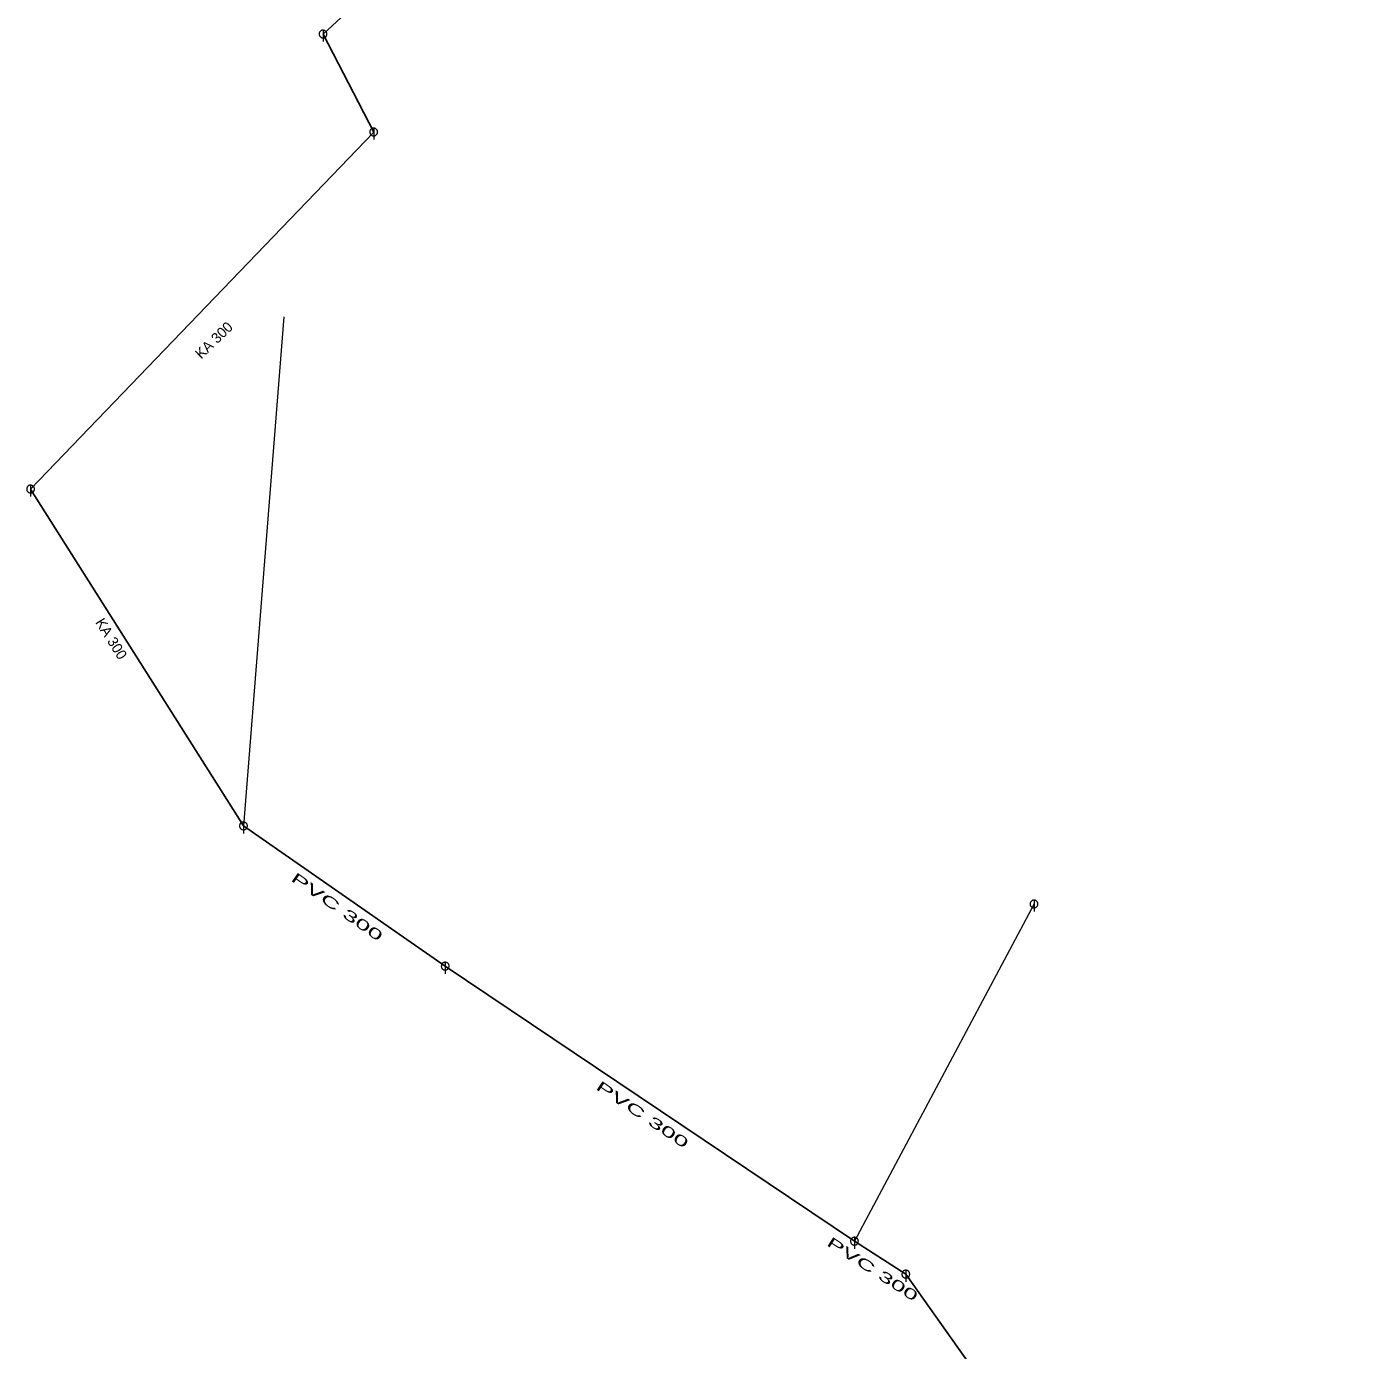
# Model space of a CAD drawing. Extents: x -687468 to -685917, y -974192 to -973456.
# Drawn here: x -686081.4 to -685995.3, y -973957.1 to -973871.6 of the extents above; entities that cross this region are included whole.
import ezdxf
from ezdxf.enums import TextEntityAlignment as Align

# ---------------------------------------------------------------- set-up
doc = ezdxf.new("R2010")
doc.units = 0
doc.header["$LTSCALE"] = 0.27
for name, color, linetype, lineweight in [('1', 7, 'Continuous', 13), ('11', 7, 'Continuous', 13), ('14', 7, 'Continuous', 25), ('22', 7, 'Continuous', 13)]:
    doc.layers.add(name, color=color, linetype=linetype, lineweight=lineweight)

msp = doc.modelspace()

# ---------------------------------------------------------------- linework, layer by layer
at = {"layer": '11'}
for p, q in [((-686064.802, -973890.376), (-686067.399, -973923.264)), ((-686016.339, -973928.308), (-686027.937, -973950.093))]:
    msp.add_line(p, q, dxfattribs=at)
at = {"layer": '14'}
for p, q in [((-686045.47, -973856.659), (-686062.261, -973872.109)), ((-686062.261, -973872.109), (-686058.989, -973878.439)), ((-686058.989, -973878.439), (-686081.151, -973901.503)), ((-686081.151, -973901.503), (-686067.399, -973923.264)), ((-686067.399, -973923.264), (-686054.369, -973932.324)), ((-686054.369, -973932.324), (-686027.937, -973950.093)), ((-686027.937, -973950.093), (-686024.619, -973952.22)), ((-686024.619, -973952.22), (-685995.262, -973993.552))]:
    msp.add_line(p, q, dxfattribs=at)
at = {"layer": '22'}
for p, q in [((-686062.26, -973871.857), (-686062.261, -973872.601)), ((-686058.988, -973878.187), (-686058.989, -973878.931)), ((-686081.15, -973901.251), (-686081.151, -973901.995)), ((-686067.398, -973923.012), (-686067.399, -973923.755)), ((-686016.338, -973928.056), (-686016.339, -973928.799)), ((-686054.368, -973932.072), (-686054.369, -973932.816)), ((-686027.936, -973949.841), (-686027.937, -973950.585)), ((-686024.618, -973951.968), (-686024.619, -973952.712))]:
    msp.add_line(p, q, dxfattribs=at)
for points in [[(-686062.009, -973872.109), (-686062.01, -973872.083), (-686062.014, -973872.057), (-686062.02, -973872.031), (-686062.03, -973872.007), (-686062.042, -973871.983), (-686062.056, -973871.961), (-686062.073, -973871.94), (-686062.091, -973871.922), (-686062.112, -973871.905), (-686062.134, -973871.891), (-686062.158, -973871.879), (-686062.182, -973871.869), (-686062.208, -973871.863), (-686062.234, -973871.859), (-686062.26, -973871.857), (-686062.286, -973871.858), (-686062.312, -973871.862), (-686062.338, -973871.868), (-686062.363, -973871.878), (-686062.386, -973871.89), (-686062.408, -973871.904), (-686062.429, -973871.921), (-686062.447, -973871.939), (-686062.464, -973871.96), (-686062.478, -973871.982), (-686062.49, -973872.006), (-686062.5, -973872.03), (-686062.507, -973872.056), (-686062.511, -973872.082), (-686062.513, -973872.108), (-686062.512, -973872.134), (-686062.508, -973872.16), (-686062.501, -973872.186), (-686062.491, -973872.211), (-686062.479, -973872.234), (-686062.465, -973872.256), (-686062.448, -973872.277), (-686062.43, -973872.295), (-686062.409, -973872.312), (-686062.387, -973872.326), (-686062.364, -973872.338), (-686062.339, -973872.348), (-686062.313, -973872.355), (-686062.287, -973872.359), (-686062.261, -973872.361), (-686062.235, -973872.36), (-686062.209, -973872.356), (-686062.183, -973872.349), (-686062.159, -973872.339), (-686062.135, -973872.327), (-686062.113, -973872.313), (-686062.092, -973872.296), (-686062.074, -973872.278), (-686062.057, -973872.257), (-686062.043, -973872.235), (-686062.031, -973872.212), (-686062.021, -973872.187), (-686062.015, -973872.161), (-686062.011, -973872.135)], [(-686058.737, -973878.439), (-686058.738, -973878.413), (-686058.742, -973878.387), (-686058.748, -973878.361), (-686058.758, -973878.337), (-686058.77, -973878.313), (-686058.784, -973878.291), (-686058.801, -973878.27), (-686058.819, -973878.252), (-686058.84, -973878.235), (-686058.862, -973878.221), (-686058.886, -973878.209), (-686058.91, -973878.199), (-686058.936, -973878.193), (-686058.962, -973878.189), (-686058.988, -973878.187), (-686059.014, -973878.188), (-686059.04, -973878.192), (-686059.066, -973878.198), (-686059.091, -973878.208), (-686059.114, -973878.22), (-686059.136, -973878.234), (-686059.157, -973878.251), (-686059.175, -973878.269), (-686059.192, -973878.29), (-686059.206, -973878.312), (-686059.218, -973878.336), (-686059.228, -973878.36), (-686059.235, -973878.386), (-686059.239, -973878.412), (-686059.24, -973878.438), (-686059.24, -973878.464), (-686059.236, -973878.49), (-686059.229, -973878.516), (-686059.219, -973878.541), (-686059.207, -973878.564), (-686059.193, -973878.586), (-686059.176, -973878.607), (-686059.158, -973878.625), (-686059.137, -973878.642), (-686059.115, -973878.656), (-686059.092, -973878.668), (-686059.067, -973878.678), (-686059.041, -973878.685), (-686059.015, -973878.689), (-686058.989, -973878.691), (-686058.963, -973878.69), (-686058.937, -973878.686), (-686058.911, -973878.679), (-686058.887, -973878.669), (-686058.863, -973878.657), (-686058.841, -973878.643), (-686058.82, -973878.626), (-686058.802, -973878.608), (-686058.785, -973878.587), (-686058.771, -973878.565), (-686058.759, -973878.542), (-686058.749, -973878.517), (-686058.743, -973878.491), (-686058.739, -973878.465)], [(-686080.899, -973901.503), (-686080.9, -973901.477), (-686080.904, -973901.451), (-686080.91, -973901.425), (-686080.92, -973901.401), (-686080.932, -973901.377), (-686080.946, -973901.355), (-686080.963, -973901.334), (-686080.981, -973901.316), (-686081.002, -973901.299), (-686081.024, -973901.285), (-686081.048, -973901.273), (-686081.072, -973901.263), (-686081.098, -973901.257), (-686081.124, -973901.253), (-686081.15, -973901.251), (-686081.176, -973901.252), (-686081.202, -973901.256), (-686081.228, -973901.262), (-686081.253, -973901.272), (-686081.276, -973901.284), (-686081.298, -973901.298), (-686081.319, -973901.315), (-686081.337, -973901.333), (-686081.354, -973901.354), (-686081.368, -973901.376), (-686081.38, -973901.4), (-686081.39, -973901.424), (-686081.397, -973901.45), (-686081.401, -973901.476), (-686081.402, -973901.502), (-686081.402, -973901.528), (-686081.398, -973901.554), (-686081.391, -973901.58), (-686081.381, -973901.605), (-686081.369, -973901.628), (-686081.355, -973901.65), (-686081.338, -973901.671), (-686081.32, -973901.689), (-686081.299, -973901.706), (-686081.277, -973901.72), (-686081.254, -973901.732), (-686081.229, -973901.742), (-686081.203, -973901.749), (-686081.177, -973901.753), (-686081.151, -973901.755), (-686081.125, -973901.754), (-686081.099, -973901.75), (-686081.073, -973901.743), (-686081.049, -973901.733), (-686081.025, -973901.721), (-686081.003, -973901.707), (-686080.982, -973901.69), (-686080.964, -973901.672), (-686080.947, -973901.651), (-686080.933, -973901.629), (-686080.921, -973901.606), (-686080.911, -973901.581), (-686080.905, -973901.555), (-686080.901, -973901.529)], [(-686067.147, -973923.264), (-686067.148, -973923.238), (-686067.152, -973923.212), (-686067.158, -973923.186), (-686067.168, -973923.162), (-686067.18, -973923.138), (-686067.194, -973923.116), (-686067.211, -973923.095), (-686067.229, -973923.077), (-686067.25, -973923.06), (-686067.272, -973923.046), (-686067.296, -973923.034), (-686067.32, -973923.024), (-686067.346, -973923.018), (-686067.372, -973923.014), (-686067.398, -973923.012), (-686067.424, -973923.013), (-686067.45, -973923.017), (-686067.476, -973923.023), (-686067.501, -973923.033), (-686067.524, -973923.045), (-686067.546, -973923.059), (-686067.567, -973923.076), (-686067.585, -973923.094), (-686067.602, -973923.115), (-686067.616, -973923.137), (-686067.628, -973923.161), (-686067.638, -973923.185), (-686067.645, -973923.211), (-686067.649, -973923.237), (-686067.651, -973923.263), (-686067.65, -973923.289), (-686067.646, -973923.315), (-686067.639, -973923.341), (-686067.629, -973923.366), (-686067.617, -973923.389), (-686067.603, -973923.411), (-686067.586, -973923.432), (-686067.568, -973923.45), (-686067.547, -973923.467), (-686067.525, -973923.481), (-686067.502, -973923.493), (-686067.477, -973923.503), (-686067.451, -973923.51), (-686067.425, -973923.514), (-686067.399, -973923.516), (-686067.373, -973923.515), (-686067.347, -973923.511), (-686067.321, -973923.504), (-686067.297, -973923.494), (-686067.273, -973923.482), (-686067.251, -973923.468), (-686067.23, -973923.451), (-686067.212, -973923.433), (-686067.195, -973923.412), (-686067.181, -973923.39), (-686067.169, -973923.367), (-686067.159, -973923.342), (-686067.153, -973923.316), (-686067.149, -973923.29)], [(-686016.087, -973928.308), (-686016.088, -973928.282), (-686016.092, -973928.256), (-686016.098, -973928.23), (-686016.108, -973928.206), (-686016.12, -973928.182), (-686016.134, -973928.16), (-686016.151, -973928.139), (-686016.169, -973928.121), (-686016.19, -973928.104), (-686016.212, -973928.09), (-686016.236, -973928.078), (-686016.26, -973928.068), (-686016.286, -973928.062), (-686016.312, -973928.058), (-686016.338, -973928.056), (-686016.364, -973928.057), (-686016.39, -973928.061), (-686016.416, -973928.067), (-686016.441, -973928.077), (-686016.464, -973928.089), (-686016.486, -973928.103), (-686016.507, -973928.12), (-686016.525, -973928.138), (-686016.542, -973928.159), (-686016.556, -973928.181), (-686016.568, -973928.205), (-686016.578, -973928.229), (-686016.585, -973928.255), (-686016.589, -973928.281), (-686016.591, -973928.307), (-686016.59, -973928.333), (-686016.586, -973928.359), (-686016.579, -973928.385), (-686016.569, -973928.41), (-686016.557, -973928.433), (-686016.543, -973928.455), (-686016.526, -973928.476), (-686016.508, -973928.494), (-686016.487, -973928.511), (-686016.465, -973928.525), (-686016.442, -973928.537), (-686016.417, -973928.547), (-686016.391, -973928.554), (-686016.365, -973928.558), (-686016.339, -973928.559), (-686016.313, -973928.559), (-686016.287, -973928.555), (-686016.261, -973928.548), (-686016.237, -973928.538), (-686016.213, -973928.526), (-686016.191, -973928.512), (-686016.17, -973928.495), (-686016.152, -973928.477), (-686016.135, -973928.456), (-686016.121, -973928.434), (-686016.109, -973928.411), (-686016.099, -973928.386), (-686016.093, -973928.36), (-686016.089, -973928.334)], [(-686054.117, -973932.324), (-686054.118, -973932.298), (-686054.122, -973932.272), (-686054.128, -973932.246), (-686054.138, -973932.222), (-686054.15, -973932.198), (-686054.164, -973932.176), (-686054.181, -973932.155), (-686054.199, -973932.137), (-686054.22, -973932.12), (-686054.242, -973932.106), (-686054.266, -973932.094), (-686054.29, -973932.084), (-686054.316, -973932.078), (-686054.342, -973932.074), (-686054.368, -973932.072), (-686054.394, -973932.073), (-686054.42, -973932.077), (-686054.446, -973932.083), (-686054.471, -973932.093), (-686054.494, -973932.105), (-686054.516, -973932.119), (-686054.537, -973932.136), (-686054.555, -973932.154), (-686054.572, -973932.175), (-686054.586, -973932.197), (-686054.598, -973932.221), (-686054.608, -973932.245), (-686054.615, -973932.271), (-686054.619, -973932.297), (-686054.62, -973932.323), (-686054.62, -973932.349), (-686054.616, -973932.375), (-686054.609, -973932.401), (-686054.599, -973932.426), (-686054.587, -973932.449), (-686054.573, -973932.471), (-686054.556, -973932.492), (-686054.538, -973932.51), (-686054.517, -973932.527), (-686054.495, -973932.541), (-686054.472, -973932.553), (-686054.447, -973932.563), (-686054.421, -973932.57), (-686054.395, -973932.574), (-686054.369, -973932.576), (-686054.343, -973932.575), (-686054.317, -973932.571), (-686054.291, -973932.564), (-686054.267, -973932.554), (-686054.243, -973932.542), (-686054.221, -973932.528), (-686054.2, -973932.511), (-686054.182, -973932.493), (-686054.165, -973932.472), (-686054.151, -973932.45), (-686054.139, -973932.427), (-686054.129, -973932.402), (-686054.123, -973932.376), (-686054.119, -973932.35)], [(-686027.685, -973950.093), (-686027.686, -973950.067), (-686027.69, -973950.041), (-686027.696, -973950.015), (-686027.706, -973949.991), (-686027.718, -973949.967), (-686027.732, -973949.945), (-686027.749, -973949.924), (-686027.767, -973949.906), (-686027.788, -973949.889), (-686027.81, -973949.875), (-686027.834, -973949.863), (-686027.858, -973949.853), (-686027.884, -973949.847), (-686027.91, -973949.843), (-686027.936, -973949.841), (-686027.962, -973949.842), (-686027.988, -973949.846), (-686028.014, -973949.852), (-686028.039, -973949.862), (-686028.062, -973949.874), (-686028.084, -973949.888), (-686028.105, -973949.905), (-686028.123, -973949.923), (-686028.14, -973949.944), (-686028.154, -973949.966), (-686028.166, -973949.99), (-686028.176, -973950.014), (-686028.183, -973950.04), (-686028.187, -973950.066), (-686028.189, -973950.092), (-686028.188, -973950.118), (-686028.184, -973950.144), (-686028.177, -973950.17), (-686028.167, -973950.195), (-686028.155, -973950.218), (-686028.141, -973950.24), (-686028.124, -973950.261), (-686028.106, -973950.279), (-686028.085, -973950.296), (-686028.063, -973950.31), (-686028.04, -973950.322), (-686028.015, -973950.332), (-686027.989, -973950.339), (-686027.963, -973950.343), (-686027.937, -973950.345), (-686027.911, -973950.344), (-686027.885, -973950.34), (-686027.859, -973950.333), (-686027.835, -973950.323), (-686027.811, -973950.311), (-686027.789, -973950.297), (-686027.768, -973950.28), (-686027.75, -973950.262), (-686027.733, -973950.241), (-686027.719, -973950.219), (-686027.707, -973950.196), (-686027.697, -973950.171), (-686027.691, -973950.145), (-686027.687, -973950.119)], [(-686024.367, -973952.22), (-686024.368, -973952.194), (-686024.372, -973952.168), (-686024.378, -973952.142), (-686024.388, -973952.118), (-686024.4, -973952.094), (-686024.414, -973952.072), (-686024.431, -973952.051), (-686024.449, -973952.033), (-686024.47, -973952.016), (-686024.492, -973952.002), (-686024.516, -973951.99), (-686024.54, -973951.98), (-686024.566, -973951.974), (-686024.592, -973951.97), (-686024.618, -973951.968), (-686024.644, -973951.969), (-686024.67, -973951.973), (-686024.696, -973951.979), (-686024.721, -973951.989), (-686024.744, -973952.001), (-686024.766, -973952.015), (-686024.787, -973952.032), (-686024.805, -973952.05), (-686024.822, -973952.071), (-686024.836, -973952.093), (-686024.848, -973952.117), (-686024.858, -973952.141), (-686024.865, -973952.167), (-686024.869, -973952.193), (-686024.87, -973952.219), (-686024.87, -973952.245), (-686024.866, -973952.271), (-686024.859, -973952.297), (-686024.849, -973952.322), (-686024.837, -973952.345), (-686024.823, -973952.367), (-686024.806, -973952.388), (-686024.788, -973952.406), (-686024.767, -973952.423), (-686024.745, -973952.437), (-686024.722, -973952.449), (-686024.697, -973952.459), (-686024.671, -973952.466), (-686024.645, -973952.47), (-686024.619, -973952.472), (-686024.593, -973952.471), (-686024.567, -973952.467), (-686024.541, -973952.46), (-686024.517, -973952.45), (-686024.493, -973952.438), (-686024.471, -973952.424), (-686024.45, -973952.407), (-686024.432, -973952.389), (-686024.415, -973952.368), (-686024.401, -973952.346), (-686024.389, -973952.323), (-686024.379, -973952.298), (-686024.373, -973952.272), (-686024.369, -973952.246)]]:
    msp.add_lwpolyline(points, close=True, dxfattribs=at)

# ---------------------------------------------------------------- texts
at = {"layer": '1'}
for rotation, p in [(44, (-686069.077, -973892.127)), (302, (-686076.218, -973911.351))]:
    msp.add_text('KA 300', height=0.6667, rotation=rotation, dxfattribs=at).set_placement(p, align=Align.CENTER)
for rotation, width, p in [(325, 1.95, (-686061.343, -973928.904)), (326, 1.95, (-686041.616, -973942.32)), (327, 1.9, (-686026.748, -973952.299))]:
    msp.add_text('PVC 300 ', height=0.6667, rotation=rotation, dxfattribs=dict(at, width=width)).set_placement(p, align=Align.CENTER)

doc.saveas('drawing.dxf')
